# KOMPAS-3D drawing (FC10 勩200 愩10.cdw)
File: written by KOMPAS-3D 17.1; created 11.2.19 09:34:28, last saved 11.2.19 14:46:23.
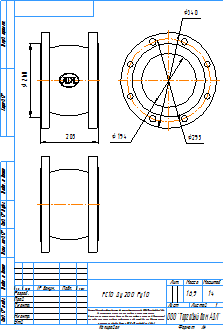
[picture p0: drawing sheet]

Sheet 1: A4, portrait

Title block, sheet 1: name: FC10 Ду200 Ру10; mass: 16,9; sheets: 1; sheet format: A4; stored path: \\adlc.lan\data\АДЛ_ПКД\3D-модели\ADL production\Гибкие вставки серии FC\FC10\KOMPAS 2D\FC10 Ду200 Ру10.cdw

Views: Вид 1
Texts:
  kka
  adl
  Рама для чертежей
  Лит-Масса-Масштаб
  Материал-Предприятие
  Масштаб
  Изм.
  Лист
  № докум.
  Подп.
  Дата
  Лит.
  Разраб.
  Пров.
  Т.контр.
  Листов
  Внимание! Данный продукт является объектом авторского права ООО «Торговый Дом АДЛ».
  Запрещается изменение, копирование, распространение
  (в том числе путем копирования на другие сайты и ресурсы в Интернете)
  или любое иное использование информации и объектов без предварительного
  согласия правообладателя (ООО «Торговый Дом АДЛ»).
  Н.контр.
  Утв.
  ООО "Торговый дом АДЛ"
  Изменение
  Номер документа
  Подпись
  Обозначение документа
  Наименование изделия
  Масса изделия по ГОСТ 2.109-73
  Порядковый номер листа
  Общее количество листов в документе
  Характер работы, выполненной лицом, подписавшим документ
  Наименование или индекс предприятия, выпускающего документ
  Инв. № подл.
  Подп. и дата
  Взам. инв. №
  Инв. № дубл.
  Инвентарный номер подлинника по ГОСТ 2.501-68
  Подпись принявшего подлинник в отдел технической документации
  Инвентарный номер подлинника, взамен которого выпущен данный подлинник
  Инвентарный номер дубликата по ГОСТ 2.502-68
  Подпись принявшего дубликат в отдел технической документации
  Справ. №
  Перв. примен.
  Обозначение документа, взамен или на основании которого выпущен данный документ
  Обозначение документа, в котором впервые записан данный документ
  Подпись лица, копировавшего чертеж
  Обозначение формата листа
  !Рама для чертежа
Dimensions and other numbers on the sheet: 205; 260; 194; 295; 340; 1:4; 1; 16,9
